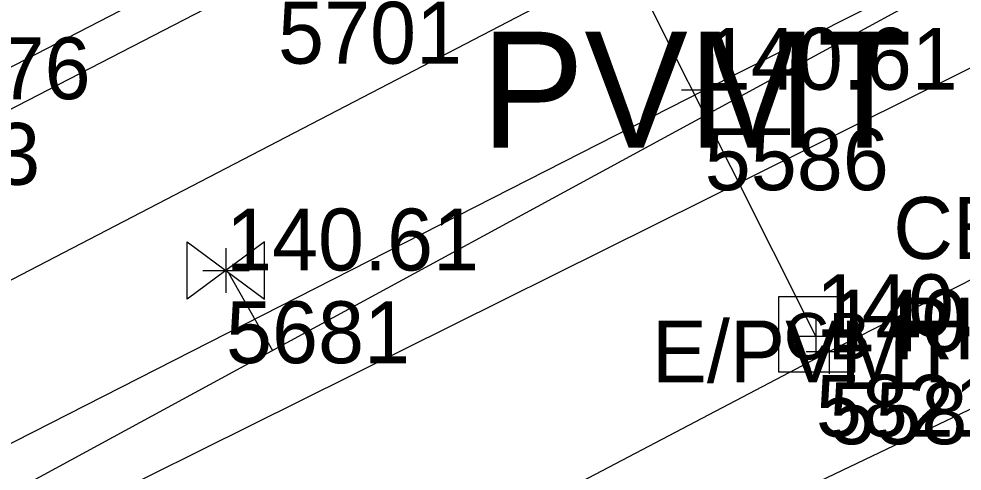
# Model space of a CAD drawing. Extents: x 13482495 to 13483389, y 311646 to 312209.
# Drawn here: x 13483137.96 to 13483186.74, y 312018.36 to 312041.76 of the extents above; entities that cross this region are included whole.
import ezdxf

# ---------------------------------------------------------------- set-up
doc = ezdxf.new("R2010")
doc.units = 0
for name, color, linetype in [('V-COMM-UNDR', 7, 'Continuous'), ('V-DOMW-MAIN', 7, 'Continuous'), ('V-DOMW-MHOL', 7, 'Continuous'), ('V-ELEC-UNDR', 7, 'Continuous'), ('V-PVMT-CNTR', 7, 'Continuous'), ('V-PVMT-ROAD', 7, 'Continuous'), ('V-PVMT-SPOT', 7, 'Continuous'), ('V-STRM-MAIN', 7, 'Continuous'), ('V-STRM-MHOL', 7, 'Continuous'), ('V-STRM-MHOL-IDEN', 7, 'Continuous'), ('V-SURV-PNTS', 7, 'Continuous'), ('V-TOPO-DRAN-SPOT', 7, 'Continuous'), ('V-TOPO-LINE-IDEN', 7, 'Continuous'), ('V-TOPO-SPOT', 7, 'Continuous'), ('V-UTIL-OVHD', 7, 'Continuous'), ('V-UTIL-SPOT', 7, 'Continuous')]:
    doc.layers.add(name, color=color, linetype=linetype)

msp = doc.modelspace()

# ---------------------------------------------------------------- linework, layer by layer
at = {"layer": 'V-COMM-UNDR'}
msp.add_lwpolyline([(13482638.43, 311773.216), (13482816.883, 311864.737), (13483031.639, 311973.194), (13483313.841, 312119.913)], dxfattribs=at)
at = {"layer": 'V-DOMW-MAIN'}
msp.add_line((13483148.799, 312028.615), (13483151.068, 312024.604), dxfattribs=at)
msp.add_lwpolyline([(13482679.686, 311784.595), (13482814.121, 311851.608), (13482868.23, 311877.786), (13483086.631, 311989.59), (13483299.889, 312105.497)], dxfattribs=at)
at = {"layer": 'V-DOMW-MHOL'}
msp.add_lwpolyline([(13483146.667, 312030.22), (13483150.667, 312027.26), (13483150.667, 312030.22), (13483146.667, 312027.26), (13483146.667, 312030.22)], dxfattribs=at)
at = {"layer": 'V-ELEC-UNDR'}
msp.add_lwpolyline([(13483136.817, 311997.525), (13483275.634, 312063.845), (13483295.351, 312065.833)], dxfattribs=at)
at = {"layer": 'V-PVMT-CNTR'}
msp.add_lwpolyline([(13482583.662, 311737.164), (13482615.839, 311753.602), (13482631.764, 311761.327), (13482644.15, 311768.11), (13482660.198, 311776.177), (13482708.876, 311801.215), (13482756.857, 311825.709), (13482802.864, 311849.141), (13482850.908, 311873.114), (13482897.465, 311897.251), (13482945.27, 311921.454), (13482988.058, 311943.315), (13483031.887, 311965.625), (13483078.612, 311989.652), (13483123.69, 312012.726), (13483173.425, 312038.092), (13483222.972, 312063.092), (13483269.032, 312086.568), (13483297.768, 312101.095)], dxfattribs=at)
at = {"layer": 'V-PVMT-ROAD'}
for points in [[(13483046.678, 311990.555), (13483079.211, 312006.888), (13483099.452, 312017.279), (13483114.671, 312025.287), (13483151.358, 312044.239), (13483167.233, 312052.433), (13483217.784, 312077.641), (13483241.711, 312089.928), (13483254.89, 312096.387), (13483267.926, 312103.062), (13483277.817, 312108.173), (13483290.977, 312115.044), (13483305.237, 312122.083), (13483309.354, 312124.167), (13483313.224, 312125.961), (13483313.468, 312125.194), (13483324.552, 312130.515), (13483328.35, 312132.225), (13483330.471, 312133.097), (13483331.734, 312133.829), (13483332.523, 312134.417), (13483333.988, 312135.742), (13483335.834, 312137.796), (13483336.653, 312138.925)], [(13483042.872, 311954.487), (13483052.824, 311959.669), (13483062.264, 311964.61), (13483069.682, 311968.382), (13483086.551, 311976.832), (13483087.165, 311977.146), (13483105.583, 311986.557), (13483106.143, 311986.556), (13483133.156, 312000.488), (13483146.508, 312007.292), (13483157.76, 312012.932), (13483179.868, 312024.55), (13483204.425, 312037.004)]]:
    msp.add_lwpolyline(points, dxfattribs=at)
at = {"layer": 'V-PVMT-SPOT'}
for p, q in [((13483173.425, 312039.252), (13483173.425, 312036.932)), ((13483172.225, 312038.092), (13483174.625, 312038.092)), ((13483179.868, 312025.71), (13483179.868, 312023.39)), ((13483178.668, 312024.55), (13483181.068, 312024.55))]:
    msp.add_line(p, q, dxfattribs=at)
at = {"layer": 'V-STRM-MAIN'}
msp.add_line((13483179.173, 312025.338), (13483166.798, 312050.026), dxfattribs=at)
msp.add_lwpolyline([(13483018.553, 311955.79), (13483095.083, 311993.466), (13483335.462, 312112.939)], dxfattribs=at)
at = {"layer": 'V-STRM-MHOL'}
for p, q in [((13483177.248, 312027.393), (13483181.168, 312027.393)), ((13483177.248, 312023.473), (13483177.248, 312027.393)), ((13483181.168, 312027.393), (13483181.168, 312023.473)), ((13483181.168, 312023.473), (13483177.248, 312023.473))]:
    msp.add_line(p, q, dxfattribs=at)
msp.add_lwpolyline([(13483177.248, 312027.393), (13483181.168, 312027.393), (13483181.168, 312023.473), (13483177.248, 312023.473)], close=True, dxfattribs=at)
at = {"layer": 'V-TOPO-DRAN-SPOT'}
for p, q in [((13483179.173, 312026.498), (13483179.173, 312024.178)), ((13483177.973, 312025.338), (13483180.373, 312025.338))]:
    msp.add_line(p, q, dxfattribs=at)
at = {"layer": 'V-UTIL-OVHD'}
msp.add_lwpolyline([(13483118.7, 312029.554), (13483287.396, 312116.623)], dxfattribs=at)
at = {"layer": 'V-UTIL-SPOT'}
for p, q in [((13483148.667, 312029.9), (13483148.667, 312027.58)), ((13483147.467, 312028.74), (13483149.867, 312028.74))]:
    msp.add_line(p, q, dxfattribs=at)

# ---------------------------------------------------------------- texts
at = {"layer": 'V-PVMT-SPOT'}
for s, p in [('140.61', (13483173.425, 312038.092)), ('140.20', (13483179.868, 312024.55))]:
    msp.add_text(s, height=3.2, dxfattribs=at).set_placement(p)
at = {"layer": 'V-STRM-MHOL'}
msp.add_text('CB', height=2.4, rotation=360, dxfattribs=at).set_placement((13483177.526, 312024.138))
at = {"layer": 'V-STRM-MHOL-IDEN'}
for s, p in [('CB#121', (13483183.173, 312029.338)), ('RIM 140.24', (13483183.173, 312024.138))]:
    msp.add_text(s, height=3.2, dxfattribs=at).set_placement(p)
at = {"layer": 'V-SURV-PNTS'}
for s, p in [('5701', (13483151.358, 312039.439)), ('5586', (13483173.425, 312032.892)), ('5681', (13483148.667, 312023.94)), ('5821', (13483179.173, 312020.138)), ('5589', (13483179.868, 312019.75))]:
    msp.add_text(s, height=3.2, dxfattribs=at).set_placement(p)
at = {"layer": 'V-TOPO-DRAN-SPOT'}
msp.add_text('140.24', height=3.2, dxfattribs=at).set_placement((13483179.173, 312025.338))
at = {"layer": 'V-TOPO-LINE-IDEN'}
for s, height, p in [('PVMT', 6, (13483161.85, 312035.092)), ('E/PVMT', 3.2, (13483170.684, 312022.95))]:
    msp.add_text(s, height=height, dxfattribs=at).set_placement(p)
at = {"layer": 'V-TOPO-SPOT'}
msp.add_text('140.76', height=3.2, dxfattribs=at).set_placement((13483128.577, 312037.601))
at = {"layer": 'V-UTIL-SPOT'}
for s, p in [('140.63', (13483125.971, 312033.172)), ('140.61', (13483148.667, 312028.74))]:
    msp.add_text(s, height=3.2, dxfattribs=at).set_placement(p)

doc.saveas('drawing.dxf')
